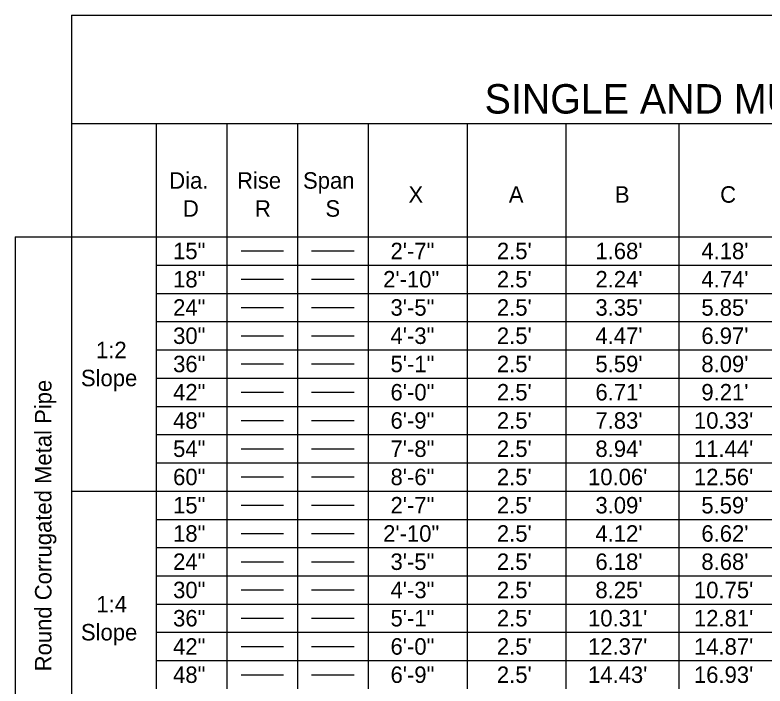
# Model space of a CAD drawing. Extents: x 1.7 to 14.4, y 0 to 7.8.
# Drawn here: x 1.7 to 4.886, y 4.902 to 7.752 of the extents above; entities that cross this region are included whole.
import ezdxf

# ---------------------------------------------------------------- set-up
doc = ezdxf.new("R2010")
doc.units = 0
doc.layers.add('Table', color=7, linetype='Continuous')

msp = doc.modelspace()

# ---------------------------------------------------------------- linework, layer by layer
at = {"layer": 'Table'}
for p, q in [((1.94, 7.7524), (13.46, 7.7524)), ((2.66, 6.75), (2.84, 6.75)), ((2.96, 6.75), (3.14, 6.75)), ((2.66, 6.63), (2.84, 6.63)), ((2.96, 6.63), (3.14, 6.63)), ((2.66, 6.51), (2.84, 6.51)), ((2.96, 6.51), (3.14, 6.51)), ((2.66, 6.39), (2.84, 6.39)), ((2.96, 6.39), (3.14, 6.39)), ((2.66, 6.27), (2.84, 6.27)), ((2.96, 6.27), (3.14, 6.27)), ((2.66, 6.15), (2.84, 6.15)), ((2.96, 6.15), (3.14, 6.15)), ((2.66, 6.03), (2.84, 6.03)), ((2.96, 6.03), (3.14, 6.03)), ((2.66, 5.91), (2.84, 5.91)), ((2.96, 5.91), (3.14, 5.91)), ((2.66, 5.79), (2.84, 5.79)), ((2.96, 5.79), (3.14, 5.79)), ((2.66, 5.67), (2.84, 5.67)), ((2.96, 5.67), (3.14, 5.67)), ((2.66, 5.55), (2.84, 5.55)), ((2.96, 5.55), (3.14, 5.55)), ((2.66, 5.43), (2.84, 5.43)), ((2.96, 5.43), (3.14, 5.43)), ((2.66, 5.31), (2.84, 5.31)), ((2.96, 5.31), (3.14, 5.31)), ((2.66, 5.19), (2.84, 5.19)), ((2.96, 5.19), (3.14, 5.19)), ((2.66, 5.07), (2.84, 5.07)), ((2.96, 5.07), (3.14, 5.07)), ((2.66, 4.95), (2.84, 4.95)), ((2.96, 4.95), (3.14, 4.95))]:
    msp.add_line(p, q, dxfattribs=at)
for points in [[(1.94, 7.7524), (1.94, 7.17), (1.94, 6.81), (1.94, 5.73), (1.94, 4.65), (1.94, 3.57), (1.94, 2.49)], [(13.46, 7.29), (11.78, 7.29), (10.1, 7.29), (8.42, 7.29), (8.06, 7.29), (6.38, 7.29), (6.02, 7.29), (5.66, 7.29), (5.3, 7.29), (4.94, 7.29), (4.52, 7.29), (4.04, 7.29), (3.62, 7.29), (3.2, 7.29), (2.9, 7.29), (2.6, 7.29), (2.3, 7.29), (1.94, 7.29)], [(2.3, 7.29), (2.3, 6.81), (2.3, 6.69), (2.3, 6.57), (2.3, 6.45), (2.3, 6.33), (2.3, 6.21), (2.3, 6.09), (2.3, 5.97), (2.3, 5.85), (2.3, 5.73), (2.3, 5.61), (2.3, 5.49), (2.3, 5.37), (2.3, 5.25), (2.3, 5.13), (2.3, 5.01), (2.3, 4.89)], [(2.6, 7.29), (2.6, 6.81), (2.6, 6.69), (2.6, 6.57), (2.6, 6.45), (2.6, 6.33), (2.6, 6.21), (2.6, 6.09), (2.6, 5.97), (2.6, 5.85), (2.6, 5.73), (2.6, 5.61), (2.6, 5.49), (2.6, 5.37), (2.6, 5.25), (2.6, 5.13), (2.6, 5.01), (2.6, 4.89)], [(2.9, 7.29), (2.9, 6.81), (2.9, 6.69), (2.9, 6.57), (2.9, 6.45), (2.9, 6.33), (2.9, 6.21), (2.9, 6.09), (2.9, 5.97), (2.9, 5.85), (2.9, 5.73), (2.9, 5.61), (2.9, 5.49), (2.9, 5.37), (2.9, 5.25), (2.9, 5.13), (2.9, 5.01), (2.9, 4.89)], [(3.2, 7.29), (3.2, 6.81), (3.2, 6.69), (3.2, 6.57), (3.2, 6.45), (3.2, 6.33), (3.2, 6.21), (3.2, 6.09), (3.2, 5.97), (3.2, 5.85), (3.2, 5.73), (3.2, 5.61), (3.2, 5.49), (3.2, 5.37), (3.2, 5.25), (3.2, 5.13), (3.2, 5.01), (3.2, 4.89)], [(3.62, 7.29), (3.62, 6.81), (3.62, 6.69), (3.62, 6.57), (3.62, 6.45), (3.62, 6.33), (3.62, 6.21), (3.62, 6.09), (3.62, 5.97), (3.62, 5.85), (3.62, 5.73), (3.62, 5.61), (3.62, 5.49), (3.62, 5.37), (3.62, 5.25), (3.62, 5.13), (3.62, 5.01), (3.62, 4.89)], [(4.04, 7.29), (4.04, 6.81), (4.04, 6.69), (4.04, 6.57), (4.04, 6.45), (4.04, 6.33), (4.04, 6.21), (4.04, 6.09), (4.04, 5.97), (4.04, 5.85), (4.04, 5.73), (4.04, 5.61), (4.04, 5.49), (4.04, 5.37), (4.04, 5.25), (4.04, 5.13), (4.04, 5.01), (4.04, 4.89)], [(4.52, 7.29), (4.52, 6.81), (4.52, 6.69), (4.52, 6.57), (4.52, 6.45), (4.52, 6.33), (4.52, 6.21), (4.52, 6.09), (4.52, 5.97), (4.52, 5.85), (4.52, 5.73), (4.52, 5.61), (4.52, 5.49), (4.52, 5.37), (4.52, 5.25), (4.52, 5.13), (4.52, 5.01), (4.52, 4.89)], [(1.7, 6.81), (1.94, 6.81), (2.3, 6.81), (2.6, 6.81), (2.9, 6.81), (3.2, 6.81), (3.62, 6.81), (4.04, 6.81), (4.52, 6.81), (4.94, 6.81), (5.3, 6.81), (5.66, 6.81), (6.02, 6.81), (6.38, 6.81), (6.8, 6.81), (7.22, 6.81), (7.64, 6.81), (8.06, 6.81), (8.42, 6.81)], [(1.7, 6.81), (1.7, 4.65), (1.7, 2.49)], [(2.3, 6.69), (2.6, 6.69), (2.9, 6.69), (3.2, 6.69), (3.62, 6.69), (4.04, 6.69), (4.52, 6.69), (4.94, 6.69), (5.3, 6.69), (5.66, 6.69), (6.02, 6.69), (6.38, 6.69), (6.8, 6.69), (7.22, 6.69), (7.64, 6.69), (8.06, 6.69), (8.42, 6.69)], [(2.3, 6.57), (2.6, 6.57), (2.9, 6.57), (3.2, 6.57), (3.62, 6.57), (4.04, 6.57), (4.52, 6.57), (4.94, 6.57), (5.3, 6.57), (5.66, 6.57), (6.02, 6.57), (6.38, 6.57), (6.8, 6.57), (7.22, 6.57), (7.64, 6.57), (8.06, 6.57), (8.42, 6.57)], [(2.3, 6.45), (2.6, 6.45), (2.9, 6.45), (3.2, 6.45), (3.62, 6.45), (4.04, 6.45), (4.52, 6.45), (4.94, 6.45), (5.3, 6.45), (5.66, 6.45), (6.02, 6.45), (6.38, 6.45), (6.8, 6.45), (7.22, 6.45), (7.64, 6.45), (8.06, 6.45), (8.42, 6.45)], [(2.3, 6.33), (2.6, 6.33), (2.9, 6.33), (3.2, 6.33), (3.62, 6.33), (4.04, 6.33), (4.52, 6.33), (4.94, 6.33), (5.3, 6.33), (5.66, 6.33), (6.02, 6.33), (6.38, 6.33), (6.8, 6.33), (7.22, 6.33), (7.64, 6.33), (8.06, 6.33), (8.42, 6.33)], [(2.3, 6.21), (2.6, 6.21), (2.9, 6.21), (3.2, 6.21), (3.62, 6.21), (4.04, 6.21), (4.52, 6.21), (4.94, 6.21), (5.3, 6.21), (5.66, 6.21), (6.02, 6.21), (6.38, 6.21), (6.8, 6.21), (7.22, 6.21), (7.64, 6.21), (8.06, 6.21), (8.42, 6.21)], [(2.3, 6.09), (2.6, 6.09), (2.9, 6.09), (3.2, 6.09), (3.62, 6.09), (4.04, 6.09), (4.52, 6.09), (4.94, 6.09), (5.3, 6.09), (5.66, 6.09), (6.02, 6.09), (6.38, 6.09), (6.8, 6.09), (7.22, 6.09), (7.64, 6.09), (8.06, 6.09), (8.42, 6.09)], [(2.3, 5.97), (2.6, 5.97), (2.9, 5.97), (3.2, 5.97), (3.62, 5.97), (4.04, 5.97), (4.52, 5.97), (4.94, 5.97), (5.3, 5.97), (5.66, 5.97), (6.02, 5.97), (6.38, 5.97), (6.8, 5.97), (7.22, 5.97), (7.64, 5.97), (8.06, 5.97), (8.42, 5.97)], [(2.3, 5.85), (2.6, 5.85), (2.9, 5.85), (3.2, 5.85), (3.62, 5.85), (4.04, 5.85), (4.52, 5.85), (4.94, 5.85), (5.3, 5.85), (5.66, 5.85), (6.02, 5.85), (6.38, 5.85), (6.8, 5.85), (7.22, 5.85), (7.64, 5.85), (8.06, 5.85), (8.42, 5.85)], [(1.94, 5.73), (2.3, 5.73), (2.6, 5.73), (2.9, 5.73), (3.2, 5.73), (3.62, 5.73), (4.04, 5.73), (4.52, 5.73), (4.94, 5.73), (5.3, 5.73), (5.66, 5.73), (6.02, 5.73), (6.38, 5.73), (6.8, 5.73), (7.22, 5.73), (7.64, 5.73), (8.06, 5.73), (8.42, 5.73)], [(2.3, 5.61), (2.6, 5.61), (2.9, 5.61), (3.2, 5.61), (3.62, 5.61), (4.04, 5.61), (4.52, 5.61), (4.94, 5.61), (5.3, 5.61), (5.66, 5.61), (6.02, 5.61), (6.38, 5.61), (6.8, 5.61), (7.22, 5.61), (7.64, 5.61), (8.06, 5.61), (8.42, 5.61)], [(2.3, 5.49), (2.6, 5.49), (2.9, 5.49), (3.2, 5.49), (3.62, 5.49), (4.04, 5.49), (4.52, 5.49), (4.94, 5.49), (5.3, 5.49), (5.66, 5.49), (6.02, 5.49), (6.38, 5.49), (6.8, 5.49), (7.22, 5.49), (7.64, 5.49), (8.06, 5.49), (8.42, 5.49)], [(2.3, 5.37), (2.6, 5.37), (2.9, 5.37), (3.2, 5.37), (3.62, 5.37), (4.04, 5.37), (4.52, 5.37), (4.94, 5.37), (5.3, 5.37), (5.66, 5.37), (6.02, 5.37), (6.38, 5.37), (6.8, 5.37), (7.22, 5.37), (7.64, 5.37), (8.06, 5.37), (8.42, 5.37)], [(2.3, 5.25), (2.6, 5.25), (2.9, 5.25), (3.2, 5.25), (3.62, 5.25), (4.04, 5.25), (4.52, 5.25), (4.94, 5.25), (5.3, 5.25), (5.66, 5.25), (6.02, 5.25), (6.38, 5.25), (6.8, 5.25), (7.22, 5.25), (7.64, 5.25), (8.06, 5.25), (8.42, 5.25)], [(2.3, 5.13), (2.6, 5.13), (2.9, 5.13), (3.2, 5.13), (3.62, 5.13), (4.04, 5.13), (4.52, 5.13), (4.94, 5.13), (5.3, 5.13), (5.66, 5.13), (6.02, 5.13), (6.38, 5.13), (6.8, 5.13), (7.22, 5.13), (7.64, 5.13), (8.06, 5.13), (8.42, 5.13)], [(2.3, 5.01), (2.6, 5.01), (2.9, 5.01), (3.2, 5.01), (3.62, 5.01), (4.04, 5.01), (4.52, 5.01), (4.94, 5.01), (5.3, 5.01), (5.66, 5.01), (6.02, 5.01), (6.38, 5.01), (6.8, 5.01), (7.22, 5.01), (7.64, 5.01), (8.06, 5.01), (8.42, 5.01)]]:
    msp.add_lwpolyline(points, dxfattribs=at)

# ---------------------------------------------------------------- texts
for s, height, p in [('SINGLE AND MULTIPLE CORRUGATED METAL PIPE DIMENSIONS AND QUANTITIES', 0.125, (3.6948, 7.3337)), ('Dia.', 0.07, (2.3552, 7.0145)), ('Rise', 0.07, (2.6431, 7.0145)), ('Span', 0.07, (2.9234, 7.0145)), ('X', 0.07, (3.3712, 6.955)), ('A', 0.07, (3.7975, 6.955)), ('B', 0.07, (4.2483, 6.955)), ('C', 0.07, (4.6952, 6.955)), ('D', 0.07, (2.4134, 6.8955)), ('R', 0.07, (2.7192, 6.8955)), ('S', 0.07, (3.0186, 6.8955)), ('1:2', 0.07, (2.0441, 6.2945)), ('Slope', 0.07, (1.98, 6.1755)), ('1:4', 0.07, (2.0455, 5.2145)), ('Slope', 0.07, (1.98, 5.0955))]:
    msp.add_text(s, height=height, dxfattribs=at).set_placement(p)
for s, rotation, p in [('2\'-7"', 0, (3.2951, 6.715)), ("2.5'", 0, (3.7469, 6.715)), ("1.68'", 0, (4.1654, 6.715)), ("4.18'", 0, (4.6154, 6.715)), ('15"', 0, (2.3715, 6.715)), ('18"', 0, (2.3715, 6.595)), ('2\'-10"', 0, (3.2637, 6.595)), ("2.5'", 0, (3.7469, 6.595)), ("2.24'", 0, (4.1654, 6.595)), ("4.74'", 0, (4.6154, 6.595)), ('24"', 0, (2.3715, 6.475)), ('3\'-5"', 0, (3.2951, 6.475)), ("2.5'", 0, (3.7469, 6.475)), ("3.35'", 0, (4.1654, 6.475)), ("5.85'", 0, (4.6154, 6.475)), ('30"', 0, (2.3715, 6.355)), ('4\'-3"', 0, (3.2951, 6.355)), ("2.5'", 0, (3.7469, 6.355)), ("4.47'", 0, (4.1654, 6.355)), ("6.97'", 0, (4.6154, 6.355)), ('36"', 0, (2.3715, 6.235)), ('5\'-1"', 0, (3.2951, 6.235)), ("2.5'", 0, (3.7469, 6.235)), ("5.59'", 0, (4.1654, 6.235)), ("8.09'", 0, (4.6154, 6.235)), ('Round Corrugated Metal Pipe', 90, (1.855, 4.9643)), ('42"', 0, (2.3715, 6.115)), ('6\'-0"', 0, (3.2951, 6.115)), ("2.5'", 0, (3.7469, 6.115)), ("6.71'", 0, (4.1654, 6.115)), ("9.21'", 0, (4.6154, 6.115)), ('48"', 0, (2.3715, 5.995)), ('6\'-9"', 0, (3.2951, 5.995)), ("2.5'", 0, (3.7469, 5.995)), ("7.83'", 0, (4.1654, 5.995)), ("10.33'", 0, (4.584, 5.995)), ('54"', 0, (2.3715, 5.875)), ('7\'-8"', 0, (3.2951, 5.875)), ("2.5'", 0, (3.7469, 5.875)), ("8.94'", 0, (4.1654, 5.875)), ("11.44'", 0, (4.584, 5.875)), ('60"', 0, (2.3715, 5.755)), ('8\'-6"', 0, (3.2951, 5.755)), ("2.5'", 0, (3.7469, 5.755)), ("10.06'", 0, (4.134, 5.755)), ("12.56'", 0, (4.584, 5.755)), ('15"', 0, (2.3715, 5.635)), ('2\'-7"', 0, (3.2951, 5.635)), ("2.5'", 0, (3.7469, 5.635)), ("3.09'", 0, (4.1654, 5.635)), ("5.59'", 0, (4.6154, 5.635)), ('18"', 0, (2.3715, 5.515)), ('2\'-10"', 0, (3.2637, 5.515)), ("2.5'", 0, (3.7469, 5.515)), ("4.12'", 0, (4.1654, 5.515)), ("6.62'", 0, (4.6154, 5.515)), ('24"', 0, (2.3715, 5.395)), ('3\'-5"', 0, (3.2951, 5.395)), ("2.5'", 0, (3.7469, 5.395)), ("6.18'", 0, (4.1654, 5.395)), ("8.68'", 0, (4.6154, 5.395)), ('30"', 0, (2.3715, 5.275)), ('4\'-3"', 0, (3.2951, 5.275)), ("2.5'", 0, (3.7469, 5.275)), ("8.25'", 0, (4.1654, 5.275)), ("10.75'", 0, (4.584, 5.275)), ('36"', 0, (2.3715, 5.155)), ('5\'-1"', 0, (3.2951, 5.155)), ("2.5'", 0, (3.7469, 5.155)), ("10.31'", 0, (4.134, 5.155)), ("12.81'", 0, (4.584, 5.155)), ('42"', 0, (2.3715, 5.035)), ('6\'-0"', 0, (3.2951, 5.035)), ("2.5'", 0, (3.7469, 5.035)), ("12.37'", 0, (4.134, 5.035)), ("14.87'", 0, (4.584, 5.035)), ('48"', 0, (2.3715, 4.915)), ('6\'-9"', 0, (3.2951, 4.915)), ("2.5'", 0, (3.7469, 4.915)), ("14.43'", 0, (4.134, 4.915)), ("16.93'", 0, (4.584, 4.915))]:
    msp.add_text(s, height=0.07, rotation=rotation, dxfattribs=at).set_placement(p)

doc.saveas('drawing.dxf')
